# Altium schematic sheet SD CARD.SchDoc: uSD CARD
size A4; CompanyName: STMicroelectronics; Organization: Microcontrollers Division; DocumentNumber: 1; SheetNumber: 11; SheetTotal: 19
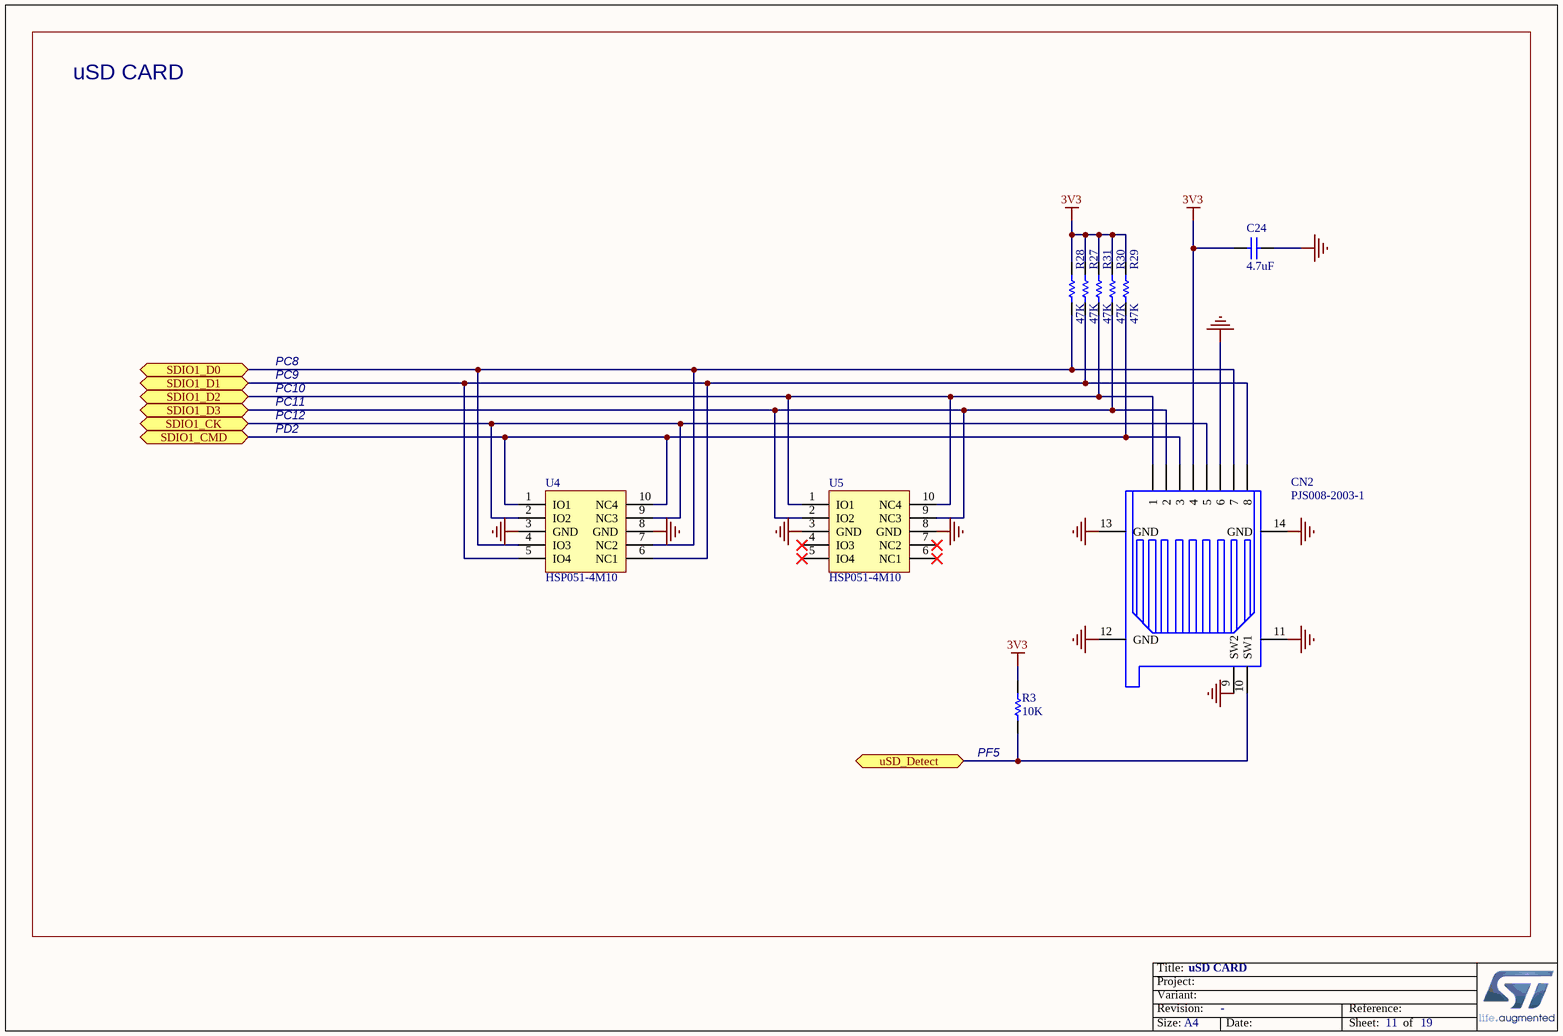
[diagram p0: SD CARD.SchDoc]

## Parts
C24  value 4.7uF  [C0603]  (hidden comment: Capacitor)
CN2  value PJS008-2003-1  [CON_MICROSD_YAMAICHI_PJS008-2003-1]  (hidden comment: microSD-PJS008-2003)
R3  value 10K  [R0603]  (hidden comment: Resistor)
R27  value 47K  [R0402]  (hidden comment: Resistor)
R28  value 47K  [R0402]  (hidden comment: Resistor)
R29  value 47K  [R0402]  (hidden comment: Resistor)
R30  value 47K  [R0402]  (hidden comment: Resistor)
R31  value 47K  [R0402]  (hidden comment: Resistor)
U4  HSP051-4M10  [ESD_UQFN-10L_2P5X1_P050]
U5  HSP051-4M10  [ESD_UQFN-10L_2P5X1_P050]

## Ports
SDIO1_CK, SDIO1_CMD, SDIO1_D0, SDIO1_D1, SDIO1_D2, SDIO1_D3, uSD_Detect

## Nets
3V3: C24.1 CN2.4 R3.2 R27.2 R28.2 R29.2 R30.2 R31.2
GND: C24.2 CN2.6 CN2.9(SW2) CN2.11(GND) CN2.12(GND) CN2.13(GND) CN2.14(GND) U4.3(GND) U4.8(GND) U5.3(GND) U5.8(GND)
SDIO1_CK: CN2.5 U4.2(IO2) U4.9(NC3) ; port SDIO1_CK
SDIO1_CMD: CN2.3 R29.1 U4.1(IO1) U4.10(NC4) ; port SDIO1_CMD
SDIO1_D0: CN2.7 R28.1 U4.4(IO3) U4.7(NC2) ; port SDIO1_D0
SDIO1_D1: CN2.8 R27.1 U4.5(IO4) U4.6(NC1) ; port SDIO1_D1
SDIO1_D2: CN2.1 R31.1 U5.1(IO1) U5.10(NC4) ; port SDIO1_D2
SDIO1_D3: CN2.2 R30.1 U5.2(IO2) U5.9(NC3) ; port SDIO1_D3
uSD_Detect: CN2.10(SW1) R3.1 ; port uSD_Detect

Not connected (* = marked no-connect by the designer): U5 4(IO3)* 5(IO4)* 6(NC1)* 7(NC2)*

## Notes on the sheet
- uSD CARD
- PC8
- PC9
- PC10
- PC11
- PC12
- PD2
- (near R3) PF5

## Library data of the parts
C24 = MCD-01121: Capacitor, MLCC, 4.7µF, 10V, X5R, 20%, 0603, T=0,8mm; Manufacturer_Part_Number: GRM188R61A475ME15; Manufacturer: MURATA; ECCN_US: EAR99; ECCN_EU: NEC; Provided_By: SUBCO
CN2 = MCD-00023: MicroSD Card Conn, Reversed-Type, Mnt Push-Push, Positionning holes; Part_Type: Connector; Manufacturer: YAMAICHI; Provided_By: SUBCO
R3 = MCD-00220: Resistor,10K,0603,1%,1/10W; Manufacturer_Part_Number: RC0603FR-0710KL; Manufacturer: YAGEO; ECCN_US: EAR99; ECCN_EU: NEC; Provided_By: SUBCO
R27-R31 = MCD-00063: Resistor,47K,0402,1%,1/16W; Manufacturer_Part_Number: RC0402FR-0747KL; Manufacturer: YAGEO; Provided_By: SUBCO
U4 U5 = MCD-00667: 4-line ESD protection for high speed lines; Part_Type: Diode; Manufacturer: STMICROELECTRONICS; BMS_Part_Number: 9179041; ECCN_US: EAR99; ECCN_EU: NEC; Provided_By: SUBCO with ST control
